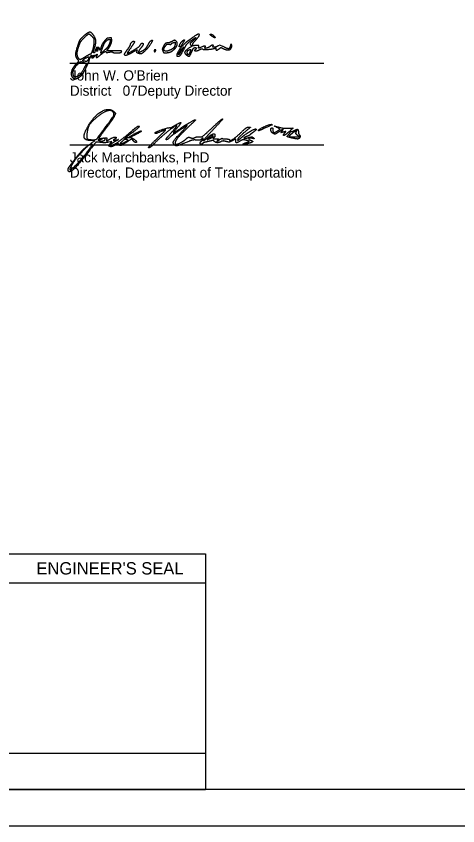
# Model space of a CAD drawing. Extents: x 0 to 36, y 0 to 22.
# Drawn here: x 23.79 to 29.88, y 0 to 11.16 of the extents above; entities that cross this region are included whole.
import ezdxf

# ---------------------------------------------------------------- set-up
doc = ezdxf.new("R2010")
doc.units = 0
for name, color, linetype in [('SH_Border', 7, 'Continuous'), ('SH_Cut_Line', 7, 'Continuous'), ('SH_Data', 7, 'Continuous'), ('SH_Text', 7, 'Continuous')]:
    doc.layers.add(name, color=color, linetype=linetype)

msp = doc.modelspace()

# ---------------------------------------------------------------- linework, layer by layer
at = {"layer": 'SH_Border'}
msp.add_lwpolyline([(1.5, 21.5), (33.5, 21.5), (33.5, 0.5), (1.5, 0.5)], close=True, dxfattribs=at)
at = {"layer": 'SH_Cut_Line'}
msp.add_lwpolyline([(0, 0), (34, 0), (34, 22), (0, 22)], close=True, dxfattribs=at)
at = {"layer": 'SH_Data'}
for p, q in [((23.6, 3.75), (26.4, 3.75)), ((26.4, 3.75), (26.4, 0.5)), ((23.6, 3.35), (26.4, 3.35)), ((23.6, 0.5), (26.4, 0.5))]:
    msp.add_line(p, q, dxfattribs=at)
msp.add_lwpolyline([(23.6, 0.5), (23.6, 1), (26.4, 1), (26.4, 0.5)], close=True, dxfattribs=at)
at = {"layer": 'SH_Text'}
for p, q in [((26.493, 10.883), (26.493, 10.883)), ((24.528, 10.516), (28.028, 10.516)), ((24.99, 9.592), (24.99, 9.592)), ((25.356, 9.502), (25.356, 9.502)), ((26.504, 9.504), (26.504, 9.504)), ((27.129, 9.591), (27.129, 9.591)), ((24.528, 9.387), (28.028, 9.387)), ((25.311, 9.46), (25.311, 9.46)), ((25.727, 9.473), (25.727, 9.473)), ((27.582, 9.485), (27.582, 9.485))]:
    msp.add_line(p, q, dxfattribs=at)
for points in [[(26.068, 10.707), (26.102, 10.74), (26.067, 10.686)], [(26.636, 10.747), (26.597, 10.763), (26.574, 10.755)], [(25.14, 10.687), (25.037, 10.687), (25.056, 10.711)], [(24.635, 10.567), (24.654, 10.547), (24.635, 10.525)], [(27.393, 9.581), (27.43, 9.603), (27.389, 9.626)], [(27.642, 9.498), (27.698, 9.498), (27.669, 9.52)], [(24.843, 9.425), (24.873, 9.446), (24.835, 9.447)], [(25.085, 9.405), (25.107, 9.437), (25.065, 9.427)], [(26.453, 9.484), (26.423, 9.459), (26.464, 9.478)]]:
    msp.add_lwpolyline(points, dxfattribs=at)
for points in [[(24.868, 10.88), (24.83, 10.941), (24.781, 10.944), (24.72, 10.89)], [(24.72, 10.89), (24.674, 10.848), (24.656, 10.819), (24.632, 10.746)], [(24.659, 10.767), (24.672, 10.801), (24.69, 10.828), (24.722, 10.861)], [(24.722, 10.861), (24.776, 10.916), (24.8, 10.92), (24.836, 10.882)], [(24.836, 10.882), (24.856, 10.86), (24.859, 10.851), (24.859, 10.808)], [(24.866, 10.716), (24.888, 10.78), (24.888, 10.846), (24.868, 10.88)], [(24.996, 10.768), (25.008, 10.8), (25.052, 10.843), (25.073, 10.843)], [(25.072, 10.862), (25.047, 10.861), (25.036, 10.855), (25.011, 10.826)], [(25.056, 10.711), (25.083, 10.747), (25.108, 10.811), (25.106, 10.838)], [(25.106, 10.838), (25.103, 10.861), (25.101, 10.863), (25.072, 10.862)], [(25.073, 10.843), (25.089, 10.843), (25.091, 10.84), (25.087, 10.825)], [(25.64, 10.819), (25.683, 10.855), (25.629, 10.748), (25.579, 10.698)], [(25.998, 10.815), (25.982, 10.831), (25.965, 10.83), (25.929, 10.811)], [(26.086, 10.826), (26.108, 10.844), (26.106, 10.822), (26.083, 10.787)], [(26.117, 10.737), (26.134, 10.77), (26.173, 10.808), (26.233, 10.85)], [(26.223, 10.869), (26.201, 10.852), (26.172, 10.832), (26.159, 10.823)], [(26.253, 10.82), (26.323, 10.895), (26.302, 10.928), (26.223, 10.869)], [(26.233, 10.85), (26.269, 10.874), (26.266, 10.858), (26.229, 10.826)], [(26.493, 10.883), (26.467, 10.899), (26.459, 10.915), (26.477, 10.914)], [(26.477, 10.914), (26.489, 10.914), (26.506, 10.901), (26.522, 10.881)], [(26.522, 10.881), (26.537, 10.862), (26.525, 10.863), (26.493, 10.883)], [(24.632, 10.746), (24.606, 10.666), (24.607, 10.597), (24.635, 10.567)], [(24.633, 10.617), (24.627, 10.646), (24.638, 10.709), (24.659, 10.767)], [(24.859, 10.808), (24.859, 10.748), (24.822, 10.635), (24.803, 10.635)], [(24.912, 10.731), (24.896, 10.731), (24.891, 10.725), (24.883, 10.701)], [(24.906, 10.715), (24.92, 10.721), (24.913, 10.702), (24.912, 10.694)], [(24.938, 10.714), (24.934, 10.725), (24.925, 10.731), (24.912, 10.731)], [(24.971, 10.769), (24.943, 10.691), (24.945, 10.695), (24.938, 10.714)], [(25.011, 10.826), (24.994, 10.807), (24.976, 10.781), (24.971, 10.769)], [(24.972, 10.709), (24.981, 10.732), (24.992, 10.758), (24.996, 10.768)], [(25.087, 10.825), (25.07, 10.769), (25.045, 10.727), (25.013, 10.698)], [(25.32, 10.651), (25.328, 10.651), (25.408, 10.693), (25.449, 10.72)], [(25.323, 10.703), (25.345, 10.732), (25.363, 10.761), (25.363, 10.767)], [(25.419, 10.811), (25.419, 10.804), (25.379, 10.739), (25.34, 10.685)], [(25.363, 10.767), (25.363, 10.782), (25.395, 10.819), (25.408, 10.819)], [(25.408, 10.819), (25.414, 10.819), (25.419, 10.815), (25.419, 10.811)], [(25.449, 10.72), (25.473, 10.735), (25.496, 10.756), (25.501, 10.767)], [(25.507, 10.723), (25.47, 10.673), (25.475, 10.658), (25.52, 10.681)], [(25.501, 10.767), (25.51, 10.787), (25.539, 10.795), (25.539, 10.776)], [(25.539, 10.776), (25.539, 10.77), (25.525, 10.746), (25.507, 10.723)], [(25.52, 10.681), (25.558, 10.701), (25.588, 10.732), (25.611, 10.776)], [(25.611, 10.776), (25.621, 10.794), (25.634, 10.814), (25.64, 10.819)], [(25.815, 10.739), (25.803, 10.712), (25.803, 10.704), (25.811, 10.683)], [(25.883, 10.795), (25.857, 10.795), (25.831, 10.773), (25.815, 10.739)], [(25.833, 10.688), (25.821, 10.699), (25.828, 10.726), (25.848, 10.753)], [(25.848, 10.753), (25.867, 10.777), (25.873, 10.78), (25.896, 10.776)], [(25.855, 10.659), (25.893, 10.659), (25.948, 10.685), (25.979, 10.718)], [(25.929, 10.811), (25.913, 10.802), (25.892, 10.795), (25.883, 10.795)], [(25.896, 10.776), (25.914, 10.773), (25.925, 10.775), (25.929, 10.782)], [(25.979, 10.78), (25.979, 10.751), (25.95, 10.713), (25.912, 10.696)], [(25.929, 10.782), (25.932, 10.788), (25.945, 10.796), (25.957, 10.799)], [(25.957, 10.799), (25.978, 10.804), (25.979, 10.803), (25.979, 10.78)], [(25.979, 10.718), (26.003, 10.744), (26.014, 10.799), (25.998, 10.815)], [(26.159, 10.823), (26.109, 10.791), (26.003, 10.659), (26.003, 10.629)], [(26.018, 10.611), (26.042, 10.611), (26.068, 10.643), (26.117, 10.737)], [(26.047, 10.739), (26.037, 10.739), (26.036, 10.743), (26.04, 10.757)], [(26.04, 10.757), (26.046, 10.777), (26.069, 10.812), (26.086, 10.826)], [(26.059, 10.745), (26.059, 10.742), (26.054, 10.739), (26.047, 10.739)], [(26.083, 10.787), (26.07, 10.768), (26.059, 10.749), (26.059, 10.745)], [(26.19, 10.734), (26.122, 10.692), (26.104, 10.649), (26.143, 10.624)], [(26.229, 10.826), (26.188, 10.79), (26.183, 10.78), (26.199, 10.763)], [(26.199, 10.763), (26.212, 10.749), (26.211, 10.747), (26.19, 10.734)], [(26.208, 10.669), (26.227, 10.712), (26.237, 10.727), (26.25, 10.729)], [(26.225, 10.769), (26.222, 10.781), (26.23, 10.796), (26.253, 10.82)], [(26.258, 10.758), (26.234, 10.754), (26.229, 10.755), (26.225, 10.769)], [(26.25, 10.729), (26.268, 10.732), (26.275, 10.712), (26.259, 10.703)], [(26.304, 10.735), (26.312, 10.754), (26.293, 10.763), (26.258, 10.758)], [(26.361, 10.743), (26.309, 10.722), (26.299, 10.72), (26.304, 10.735)], [(26.391, 10.73), (26.401, 10.747), (26.387, 10.754), (26.361, 10.743)], [(26.465, 10.748), (26.445, 10.73), (26.381, 10.714), (26.391, 10.73)], [(26.456, 10.707), (26.508, 10.712), (26.547, 10.732), (26.542, 10.707)], [(26.503, 10.747), (26.513, 10.763), (26.482, 10.764), (26.465, 10.748)], [(26.574, 10.755), (26.553, 10.738), (26.494, 10.732), (26.503, 10.747)], [(26.59, 10.715), (26.61, 10.731), (26.612, 10.731), (26.641, 10.717)], [(26.742, 10.758), (26.732, 10.715), (26.701, 10.712), (26.636, 10.747)], [(26.641, 10.717), (26.678, 10.699), (26.737, 10.698), (26.748, 10.715)], [(26.757, 10.772), (26.751, 10.778), (26.746, 10.774), (26.742, 10.758)], [(26.748, 10.715), (26.761, 10.736), (26.766, 10.763), (26.757, 10.772)], [(24.673, 10.563), (24.662, 10.563), (24.637, 10.597), (24.633, 10.617)], [(24.803, 10.635), (24.799, 10.635), (24.769, 10.618), (24.737, 10.599)], [(24.792, 10.534), (24.795, 10.563), (24.836, 10.653), (24.828, 10.592)], [(24.828, 10.592), (24.842, 10.587), (24.857, 10.596), (24.871, 10.61)], [(24.86, 10.61), (24.846, 10.599), (24.833, 10.594), (24.841, 10.606)], [(24.841, 10.606), (24.844, 10.609), (24.848, 10.613), (24.854, 10.619)], [(24.854, 10.661), (24.852, 10.663), (24.857, 10.688), (24.866, 10.716)], [(24.883, 10.701), (24.872, 10.667), (24.862, 10.653), (24.854, 10.661)], [(24.854, 10.619), (24.865, 10.629), (24.868, 10.618), (24.86, 10.61)], [(24.871, 10.61), (24.897, 10.638), (24.912, 10.642), (24.899, 10.619)], [(24.899, 10.619), (24.886, 10.594), (24.905, 10.591), (24.932, 10.614)], [(24.899, 10.69), (24.899, 10.694), (24.9, 10.7), (24.906, 10.715)], [(24.912, 10.694), (24.908, 10.677), (24.899, 10.679), (24.899, 10.69)], [(24.932, 10.614), (24.966, 10.643), (25.026, 10.687), (25.03, 10.662)], [(25.013, 10.698), (24.962, 10.653), (24.951, 10.656), (24.972, 10.709)], [(25.03, 10.662), (25.044, 10.663), (25.068, 10.667), (25.084, 10.67)], [(25.084, 10.67), (25.103, 10.674), (25.115, 10.673), (25.119, 10.667)], [(25.119, 10.667), (25.124, 10.658), (25.209, 10.655), (25.231, 10.663)], [(25.243, 10.677), (25.243, 10.684), (25.212, 10.687), (25.14, 10.687)], [(25.231, 10.663), (25.238, 10.666), (25.243, 10.672), (25.243, 10.677)], [(25.283, 10.638), (25.283, 10.644), (25.301, 10.673), (25.323, 10.703)], [(25.393, 10.663), (25.326, 10.627), (25.283, 10.617), (25.283, 10.638)], [(25.34, 10.685), (25.326, 10.666), (25.317, 10.651), (25.32, 10.651)], [(25.455, 10.679), (25.459, 10.698), (25.458, 10.698), (25.393, 10.663)], [(25.472, 10.65), (25.453, 10.657), (25.45, 10.662), (25.455, 10.679)], [(25.579, 10.698), (25.533, 10.652), (25.502, 10.639), (25.472, 10.65)], [(25.704, 10.699), (25.697, 10.699), (25.691, 10.693), (25.691, 10.686)], [(25.691, 10.686), (25.691, 10.672), (25.708, 10.674), (25.713, 10.689)], [(25.713, 10.689), (25.715, 10.694), (25.711, 10.699), (25.704, 10.699)], [(25.811, 10.683), (25.82, 10.661), (25.825, 10.659), (25.855, 10.659)], [(25.912, 10.696), (25.884, 10.682), (25.842, 10.678), (25.833, 10.688)], [(26.003, 10.629), (26.003, 10.617), (26.008, 10.611), (26.018, 10.611)], [(26.067, 10.686), (26.041, 10.642), (26.027, 10.627), (26.027, 10.644)], [(26.027, 10.644), (26.027, 10.651), (26.033, 10.661), (26.039, 10.667)], [(26.039, 10.667), (26.046, 10.672), (26.051, 10.681), (26.055, 10.687)], [(26.055, 10.687), (26.058, 10.693), (26.059, 10.702), (26.068, 10.707)], [(26.143, 10.624), (26.154, 10.616), (26.167, 10.611), (26.173, 10.611)], [(26.15, 10.647), (26.143, 10.665), (26.159, 10.696), (26.179, 10.701)], [(26.181, 10.663), (26.166, 10.632), (26.157, 10.628), (26.15, 10.647)], [(26.173, 10.611), (26.179, 10.611), (26.194, 10.637), (26.208, 10.669)], [(26.179, 10.701), (26.199, 10.706), (26.199, 10.7), (26.181, 10.663)], [(26.259, 10.703), (26.247, 10.695), (26.25, 10.683), (26.265, 10.683)], [(26.265, 10.683), (26.272, 10.683), (26.294, 10.69), (26.314, 10.7)], [(26.314, 10.7), (26.341, 10.713), (26.353, 10.715), (26.363, 10.708)], [(26.363, 10.708), (26.373, 10.702), (26.401, 10.702), (26.456, 10.707)], [(26.542, 10.707), (26.542, 10.693), (26.568, 10.698), (26.59, 10.715)], [(24.574, 10.406), (24.58, 10.429), (24.631, 10.497), (24.659, 10.52)], [(24.606, 10.495), (24.601, 10.49), (24.588, 10.472), (24.576, 10.455)], [(24.635, 10.525), (24.624, 10.513), (24.611, 10.499), (24.606, 10.495)], [(24.659, 10.52), (24.681, 10.538), (24.683, 10.538), (24.718, 10.526)], [(24.737, 10.599), (24.704, 10.579), (24.675, 10.563), (24.673, 10.563)], [(24.752, 10.54), (24.723, 10.541), (24.706, 10.548), (24.709, 10.556)], [(24.709, 10.556), (24.712, 10.566), (24.786, 10.606), (24.792, 10.601)], [(24.718, 10.526), (24.739, 10.519), (24.755, 10.511), (24.755, 10.509)], [(24.755, 10.509), (24.755, 10.507), (24.741, 10.477), (24.723, 10.442)], [(24.749, 10.445), (24.762, 10.472), (24.776, 10.499), (24.779, 10.506)], [(24.782, 10.568), (24.772, 10.547), (24.763, 10.539), (24.752, 10.54)], [(24.779, 10.506), (24.783, 10.511), (24.786, 10.521), (24.792, 10.534)], [(24.792, 10.601), (24.794, 10.599), (24.79, 10.584), (24.782, 10.568)], [(24.576, 10.455), (24.545, 10.408), (24.549, 10.327), (24.582, 10.305)], [(24.599, 10.323), (24.585, 10.323), (24.568, 10.382), (24.574, 10.406)], [(24.723, 10.442), (24.688, 10.376), (24.659, 10.341), (24.629, 10.33)], [(24.643, 10.314), (24.68, 10.334), (24.718, 10.38), (24.749, 10.445)], [(24.582, 10.305), (24.596, 10.295), (24.61, 10.298), (24.643, 10.314)], [(24.629, 10.33), (24.619, 10.326), (24.605, 10.323), (24.599, 10.323)], [(24.779, 9.643), (24.865, 9.793), (25.073, 9.909), (25.139, 9.843)], [(25.13, 9.834), (25.104, 9.876), (24.978, 9.835), (24.883, 9.753)], [(24.99, 9.592), (25.112, 9.755), (25.144, 9.812), (25.13, 9.834)], [(25.139, 9.843), (25.158, 9.825), (25.158, 9.82), (25.139, 9.781)], [(24.883, 9.753), (24.816, 9.696), (24.777, 9.632), (24.766, 9.561)], [(25.139, 9.781), (25.128, 9.758), (25.077, 9.683), (25.024, 9.613)], [(26.033, 9.601), (26.113, 9.658), (26.244, 9.735), (26.26, 9.735)], [(26.26, 9.735), (26.265, 9.735), (26.224, 9.692), (26.168, 9.64)], [(26.487, 9.621), (26.562, 9.691), (26.628, 9.747), (26.634, 9.747)], [(26.634, 9.747), (26.639, 9.747), (26.587, 9.687), (26.518, 9.614)], [(24.835, 9.447), (24.737, 9.448), (24.714, 9.53), (24.779, 9.643)], [(25.024, 9.613), (24.972, 9.544), (24.929, 9.483), (24.929, 9.478)], [(25.369, 9.569), (25.419, 9.612), (25.465, 9.647), (25.47, 9.647)], [(25.47, 9.647), (25.495, 9.648), (25.472, 9.622), (25.386, 9.555)], [(26.002, 9.654), (25.992, 9.664), (25.782, 9.497), (25.704, 9.418)], [(25.705, 9.557), (25.705, 9.567), (25.892, 9.631), (25.908, 9.625)], [(26.142, 9.654), (26.093, 9.626), (25.905, 9.494), (25.891, 9.478)], [(25.908, 9.625), (25.914, 9.624), (25.943, 9.637), (25.974, 9.655)], [(25.924, 9.554), (25.97, 9.606), (26.005, 9.651), (26.002, 9.654)], [(26.005, 9.62), (25.977, 9.588), (25.954, 9.559), (25.954, 9.554)], [(25.954, 9.554), (25.954, 9.55), (25.99, 9.571), (26.033, 9.601)], [(25.974, 9.655), (26.052, 9.701), (26.065, 9.688), (26.005, 9.62)], [(26.168, 9.64), (26.069, 9.547), (25.979, 9.438), (25.979, 9.411)], [(26.077, 9.575), (26.123, 9.624), (26.152, 9.66), (26.142, 9.654)], [(26.312, 9.499), (26.345, 9.496), (26.369, 9.513), (26.487, 9.621)], [(26.518, 9.614), (26.388, 9.476), (26.356, 9.429), (26.439, 9.497)], [(26.876, 9.474), (26.93, 9.523), (27.077, 9.613), (27.094, 9.607)], [(26.895, 9.565), (26.94, 9.609), (26.977, 9.635), (26.995, 9.634)], [(26.995, 9.634), (27.019, 9.634), (27.016, 9.628), (26.967, 9.588)], [(27.094, 9.607), (27.102, 9.604), (27.087, 9.586), (27.06, 9.566)], [(27.129, 9.591), (27.129, 9.603), (27.282, 9.674), (27.301, 9.67)], [(27.201, 9.612), (27.138, 9.584), (27.129, 9.581), (27.129, 9.591)], [(27.301, 9.67), (27.322, 9.666), (27.323, 9.666), (27.201, 9.612)], [(27.33, 9.547), (27.304, 9.561), (27.293, 9.622), (27.317, 9.622)], [(27.317, 9.622), (27.324, 9.622), (27.329, 9.608), (27.329, 9.591)], [(27.389, 9.626), (27.346, 9.65), (27.345, 9.65), (27.448, 9.624)], [(27.453, 9.577), (27.477, 9.606), (27.461, 9.602), (27.405, 9.565)], [(27.448, 9.624), (27.469, 9.618), (27.514, 9.616), (27.548, 9.618)], [(27.548, 9.618), (27.603, 9.621), (27.608, 9.619), (27.588, 9.604)], [(27.588, 9.604), (27.559, 9.583), (27.582, 9.566), (27.616, 9.584)], [(27.616, 9.584), (27.656, 9.606), (27.679, 9.6), (27.679, 9.569)], [(24.766, 9.561), (24.755, 9.488), (24.776, 9.46), (24.844, 9.46)], [(24.844, 9.46), (24.891, 9.46), (24.895, 9.464), (24.99, 9.592)], [(25.074, 9.464), (25.102, 9.484), (25.167, 9.502), (25.167, 9.49)], [(25.108, 9.385), (25.131, 9.385), (25.257, 9.474), (25.369, 9.569)], [(25.167, 9.49), (25.167, 9.485), (25.157, 9.474), (25.145, 9.466)], [(25.386, 9.555), (25.293, 9.482), (25.271, 9.46), (25.315, 9.484)], [(25.315, 9.484), (25.328, 9.491), (25.351, 9.493), (25.368, 9.489)], [(25.359, 9.497), (25.354, 9.497), (25.353, 9.499), (25.356, 9.502)], [(25.356, 9.502), (25.376, 9.52), (25.508, 9.586), (25.513, 9.58)], [(25.513, 9.58), (25.519, 9.574), (25.377, 9.497), (25.359, 9.497)], [(25.368, 9.489), (25.404, 9.479), (25.463, 9.422), (25.436, 9.422)], [(25.786, 9.572), (25.723, 9.546), (25.704, 9.542), (25.705, 9.557)], [(25.727, 9.473), (25.798, 9.541), (25.854, 9.597), (25.85, 9.597)], [(25.85, 9.597), (25.847, 9.597), (25.818, 9.586), (25.786, 9.572)], [(25.858, 9.46), (25.848, 9.46), (25.877, 9.501), (25.924, 9.554)], [(25.97, 9.389), (25.945, 9.415), (25.973, 9.465), (26.077, 9.575)], [(26.137, 9.475), (26.157, 9.493), (26.17, 9.496), (26.194, 9.487)], [(26.194, 9.487), (26.214, 9.479), (26.233, 9.48), (26.249, 9.489)], [(26.249, 9.489), (26.262, 9.496), (26.291, 9.501), (26.312, 9.499)], [(26.439, 9.497), (26.487, 9.536), (26.529, 9.547), (26.529, 9.519)], [(26.504, 9.504), (26.504, 9.517), (26.48, 9.508), (26.453, 9.484)], [(26.464, 9.478), (26.486, 9.489), (26.504, 9.501), (26.504, 9.504)], [(26.529, 9.519), (26.529, 9.51), (26.523, 9.496), (26.514, 9.487)], [(26.729, 9.458), (26.729, 9.436), (26.825, 9.497), (26.895, 9.565)], [(26.967, 9.588), (26.893, 9.527), (26.842, 9.473), (26.842, 9.456)], [(26.97, 9.505), (26.921, 9.489), (26.94, 9.475), (26.992, 9.489)], [(27.004, 9.521), (27.001, 9.517), (26.986, 9.509), (26.97, 9.505)], [(26.992, 9.489), (27.03, 9.499), (27.045, 9.499), (27.058, 9.487)], [(27.06, 9.566), (27.033, 9.545), (27.008, 9.525), (27.004, 9.521)], [(27.329, 9.591), (27.329, 9.554), (27.344, 9.552), (27.393, 9.581)], [(27.405, 9.565), (27.365, 9.539), (27.352, 9.535), (27.33, 9.547)], [(27.472, 9.565), (27.439, 9.557), (27.437, 9.558), (27.453, 9.577)], [(27.492, 9.554), (27.507, 9.572), (27.505, 9.573), (27.472, 9.565)], [(27.521, 9.545), (27.489, 9.515), (27.466, 9.522), (27.492, 9.554)], [(27.546, 9.533), (27.577, 9.566), (27.555, 9.577), (27.521, 9.545)], [(27.582, 9.485), (27.527, 9.498), (27.522, 9.505), (27.546, 9.533)], [(27.589, 9.543), (27.546, 9.512), (27.563, 9.498), (27.642, 9.498)], [(27.7, 9.492), (27.692, 9.471), (27.651, 9.468), (27.582, 9.485)], [(27.65, 9.566), (27.66, 9.591), (27.651, 9.588), (27.589, 9.543)], [(27.669, 9.52), (27.649, 9.536), (27.643, 9.549), (27.65, 9.566)], [(27.679, 9.569), (27.679, 9.553), (27.686, 9.534), (27.694, 9.526)], [(27.694, 9.526), (27.701, 9.518), (27.704, 9.503), (27.7, 9.492)], [(24.835, 9.396), (24.814, 9.417), (24.596, 9.191), (24.55, 9.101)], [(24.592, 9.183), (24.669, 9.283), (24.749, 9.36), (24.843, 9.425)], [(24.62, 9.119), (24.687, 9.188), (24.843, 9.388), (24.835, 9.396)], [(24.924, 9.425), (24.89, 9.428), (24.879, 9.418), (24.802, 9.316)], [(24.936, 9.459), (24.913, 9.458), (24.914, 9.457), (24.94, 9.447)], [(25.065, 9.427), (25.025, 9.418), (25.002, 9.417), (24.924, 9.425)], [(24.929, 9.478), (24.929, 9.474), (24.945, 9.473), (24.964, 9.478)], [(24.979, 9.473), (24.969, 9.466), (24.949, 9.46), (24.936, 9.459)], [(24.94, 9.447), (24.97, 9.435), (25.026, 9.459), (25.009, 9.477)], [(24.964, 9.478), (24.989, 9.484), (24.993, 9.482), (24.979, 9.473)], [(25.009, 9.477), (25.004, 9.481), (25.01, 9.485), (25.022, 9.485)], [(25.022, 9.485), (25.037, 9.485), (25.042, 9.479), (25.037, 9.466)], [(25.037, 9.466), (25.029, 9.443), (25.041, 9.442), (25.074, 9.464)], [(25.084, 9.365), (25.066, 9.372), (25.066, 9.376), (25.085, 9.405)], [(25.151, 9.385), (25.125, 9.37), (25.095, 9.361), (25.084, 9.365)], [(25.152, 9.436), (25.101, 9.407), (25.081, 9.385), (25.108, 9.385)], [(25.145, 9.466), (25.126, 9.452), (25.128, 9.451), (25.161, 9.455)], [(25.202, 9.399), (25.199, 9.407), (25.18, 9.402), (25.151, 9.385)], [(25.161, 9.455), (25.198, 9.461), (25.198, 9.461), (25.152, 9.436)], [(25.316, 9.428), (25.248, 9.384), (25.21, 9.374), (25.202, 9.399)], [(25.258, 9.444), (25.213, 9.403), (25.225, 9.394), (25.283, 9.424)], [(25.311, 9.46), (25.293, 9.467), (25.277, 9.462), (25.258, 9.444)], [(25.283, 9.424), (25.329, 9.448), (25.333, 9.452), (25.311, 9.46)], [(25.401, 9.447), (25.384, 9.471), (25.382, 9.471), (25.316, 9.428)], [(25.436, 9.422), (25.426, 9.422), (25.411, 9.434), (25.401, 9.447)], [(25.617, 9.348), (25.607, 9.348), (25.656, 9.405), (25.727, 9.473)], [(25.704, 9.418), (25.667, 9.379), (25.627, 9.348), (25.617, 9.348)], [(25.891, 9.478), (25.883, 9.468), (25.868, 9.46), (25.858, 9.46)], [(26.169, 9.437), (26.023, 9.379), (25.988, 9.371), (25.97, 9.389)], [(25.979, 9.411), (25.979, 9.404), (25.988, 9.397), (25.998, 9.397)], [(25.998, 9.397), (26.019, 9.397), (26.101, 9.443), (26.137, 9.475)], [(26.275, 9.454), (26.246, 9.458), (26.206, 9.451), (26.169, 9.437)], [(26.344, 9.468), (26.329, 9.454), (26.307, 9.45), (26.275, 9.454)], [(26.341, 9.397), (26.323, 9.397), (26.327, 9.43), (26.348, 9.447)], [(26.359, 9.408), (26.356, 9.402), (26.348, 9.397), (26.341, 9.397)], [(26.367, 9.476), (26.367, 9.483), (26.357, 9.48), (26.344, 9.468)], [(26.348, 9.447), (26.359, 9.456), (26.367, 9.469), (26.367, 9.476)], [(26.436, 9.435), (26.397, 9.426), (26.363, 9.414), (26.359, 9.408)], [(26.52, 9.437), (26.509, 9.448), (26.489, 9.448), (26.436, 9.435)], [(26.514, 9.487), (26.503, 9.476), (26.509, 9.472), (26.541, 9.472)], [(26.616, 9.435), (26.585, 9.418), (26.538, 9.419), (26.52, 9.437)], [(26.541, 9.472), (26.579, 9.472), (26.581, 9.47), (26.565, 9.451)], [(26.565, 9.451), (26.553, 9.436), (26.56, 9.438), (26.587, 9.457)], [(26.587, 9.457), (26.609, 9.472), (26.629, 9.481), (26.633, 9.477)], [(26.681, 9.435), (26.654, 9.442), (26.631, 9.442), (26.616, 9.435)], [(26.633, 9.477), (26.637, 9.473), (26.66, 9.47), (26.685, 9.47)], [(26.77, 9.446), (26.732, 9.427), (26.714, 9.425), (26.681, 9.435)], [(26.685, 9.47), (26.709, 9.47), (26.729, 9.465), (26.729, 9.458)], [(26.817, 9.446), (26.817, 9.469), (26.816, 9.469), (26.77, 9.446)], [(26.879, 9.443), (26.834, 9.416), (26.817, 9.417), (26.817, 9.446)], [(26.842, 9.456), (26.842, 9.449), (26.857, 9.457), (26.876, 9.474)], [(26.962, 9.451), (26.923, 9.461), (26.906, 9.459), (26.879, 9.443)], [(26.998, 9.41), (26.952, 9.395), (26.904, 9.4), (26.948, 9.416)], [(26.948, 9.416), (26.962, 9.421), (26.982, 9.428), (26.992, 9.432)], [(26.992, 9.432), (27.003, 9.436), (26.992, 9.443), (26.962, 9.451)], [(27.039, 9.479), (27.002, 9.488), (26.989, 9.465), (27.023, 9.452)], [(27.023, 9.452), (27.054, 9.44), (27.045, 9.425), (26.998, 9.41)], [(27.058, 9.487), (27.07, 9.474), (27.067, 9.472), (27.039, 9.479)], [(24.802, 9.316), (24.65, 9.114), (24.504, 8.985), (24.504, 9.052)], [(24.504, 9.052), (24.504, 9.062), (24.544, 9.121), (24.592, 9.183)], [(24.55, 9.101), (24.518, 9.04), (24.55, 9.048), (24.62, 9.119)]]:
    msp.add_open_spline(points, degree=2, dxfattribs=at)

# ---------------------------------------------------------------- texts
at = {"layer": 'SH_Data'}
msp.add_text("ENGINEER'S SEAL", height=0.17, dxfattribs=at).set_placement((24.068, 3.465))
at = {"layer": 'SH_Text'}
for s, p in [("John W. O'Brien", (24.528, 10.276)), ('District       Deputy Director', (24.528, 10.066)), ('              07', (24.528, 10.066)), ('Jack Marchbanks, PhD', (24.528, 9.147)), ('Director, Department of Transportation', (24.528, 8.937))]:
    msp.add_text(s, height=0.14, dxfattribs=at).set_placement(p)

doc.saveas('drawing.dxf')
